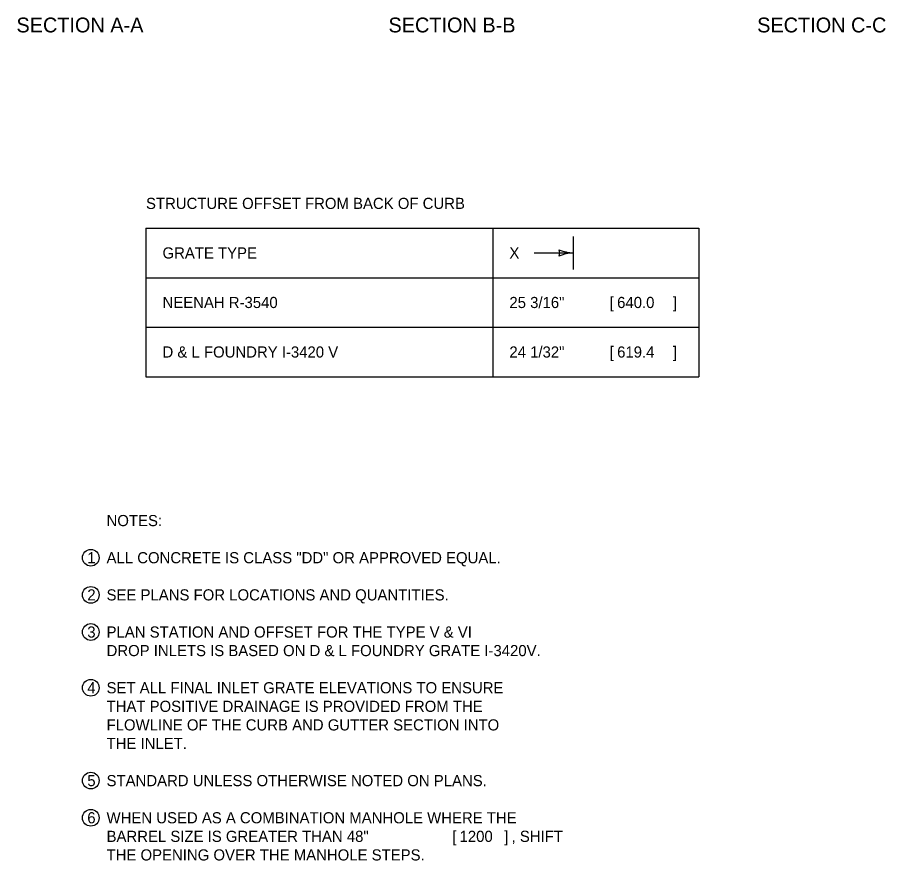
# Model space of a CAD drawing. Extents: x 49991.4 to 50041.6, y 49987.6 to 50011.4.
# Drawn here: x 50031.324 to 50035.997, y 49988.642 to 49993.182 of the extents above; entities that cross this region are included whole.
import ezdxf

# ---------------------------------------------------------------- set-up
doc = ezdxf.new("R2010")
doc.units = 0
doc.layers.add('Level 2', color=7, linetype='Continuous')
doc.layers.add('Level 3', color=7, linetype='Continuous')

msp = doc.modelspace()

# ---------------------------------------------------------------- linework, layer by layer
at = {"layer": 'Level 2'}
for p, q in [((50032.0163, 49992.0468), (50032.0163, 49991.2468)), ((50032.0163, 49992.0468), (50034.9914, 49992.0468)), ((50033.883, 49992.0468), (50033.883, 49991.2468)), ((50034.9914, 49992.0468), (50034.9914, 49991.2468)), ((50032.0163, 49991.7802), (50034.9914, 49991.7802)), ((50032.0163, 49991.5135), (50034.9914, 49991.5135)), ((50032.0163, 49991.2468), (50034.9914, 49991.2468))]:
    msp.add_line(p, q, dxfattribs=at)
for centre in [(50031.7191, 49990.2727), (50031.7191, 49990.0727), (50031.7191, 49989.8727), (50031.7191, 49989.5727), (50031.7191, 49989.0727), (50031.7191, 49988.8727)]:
    msp.add_circle(centre, 0.045, dxfattribs=at)
at = {"layer": 'Level 3'}
for p, q in [((50034.3163, 49991.8246), (50034.3163, 49992.0024)), ((50034.1047, 49991.9135), (50034.3163, 49991.9135))]:
    msp.add_line(p, q, dxfattribs=at)
for centre, radius, start, end in [((50034.3254, 49992.1356), 0.2223, 247.456, 267.6395), ((50034.1881, 49991.9135), 0.0548, 342.1388, 17.8612), ((50034.3278, 49991.6808), 0.233, 92.8273, 112.0772)]:
    msp.add_arc(centre, radius, start, end, dxfattribs=at)

# ---------------------------------------------------------------- texts
at = {"layer": 'Level 2'}
for s, height, p in [('SECTION A-A', 0.08, (50031.3192, 49993.1006)), ('SECTION B-B', 0.08, (50033.3212, 49993.1006)), ('SECTION C-C', 0.08, (50035.3052, 49993.1006)), ('STRUCTURE OFFSET FROM BACK OF CURB', 0.06, (50032.0163, 49992.1502)), ('GRATE TYPE       ', 0.06, (50032.1052, 49991.8835)), ('X', 0.06, (50033.9719, 49991.8835)), ('NEENAH R-3540', 0.06, (50032.1052, 49991.6168)), ('25 3/16" ', 0.06, (50033.9719, 49991.6168)), ('[', 0.06, (50034.5119, 49991.6168)), ('640.0', 0.06, (50034.5516, 49991.6168)), (']', 0.06, (50034.8516, 49991.6168)), ('D & L FOUNDRY I-3420 V', 0.06, (50032.1052, 49991.3502)), ('24 1/32" ', 0.06, (50033.9719, 49991.3502)), ('[', 0.06, (50034.5119, 49991.3502)), ('619.4', 0.06, (50034.5516, 49991.3502)), (']', 0.06, (50034.8516, 49991.3502)), ('NOTES:', 0.06, (50031.8041, 49990.4427)), ('1', 0.06, (50031.7004, 49990.2427)), ('ALL CONCRETE IS CLASS "DD" OR APPROVED EQUAL.', 0.06, (50031.8041, 49990.2427)), ('2', 0.06, (50031.7004, 49990.0427)), ('SEE PLANS FOR LOCATIONS AND QUANTITIES.', 0.06, (50031.8041, 49990.0427)), ('3', 0.06, (50031.7004, 49989.8427)), ('PLAN STATION AND OFFSET FOR THE TYPE V & VI', 0.06, (50031.8041, 49989.8427)), ('DROP INLETS IS BASED ON D & L FOUNDRY GRATE I-3420V.', 0.06, (50031.8041, 49989.7427)), ('4', 0.06, (50031.7004, 49989.5427)), ('SET ALL FINAL INLET GRATE ELEVATIONS TO ENSURE', 0.06, (50031.8041, 49989.5427)), ('THAT POSITIVE DRAINAGE IS PROVIDED FROM THE ', 0.06, (50031.8041, 49989.4427)), ('FLOWLINE OF THE CURB AND GUTTER SECTION INTO', 0.06, (50031.8041, 49989.3427)), ('THE INLET.', 0.06, (50031.8041, 49989.2427)), ('5', 0.06, (50031.7004, 49989.0427)), ('STANDARD UNLESS OTHERWISE NOTED ON PLANS.', 0.06, (50031.8041, 49989.0427)), ('6', 0.06, (50031.7004, 49988.8427)), ('WHEN USED AS A COMBINATION MANHOLE WHERE THE', 0.06, (50031.8041, 49988.8427)), ('BARREL SIZE IS GREATER THAN 48" ', 0.06, (50031.8041, 49988.7427)), ('[', 0.06, (50033.6641, 49988.7427)), ('1200', 0.06, (50033.7038, 49988.7427)), (']', 0.06, (50033.9438, 49988.7427)), (', SHIFT', 0.06, (50033.9835, 49988.7427)), ('THE OPENING OVER THE MANHOLE STEPS.', 0.06, (50031.8041, 49988.6427))]:
    msp.add_text(s, height=height, dxfattribs=at).set_placement(p)

doc.saveas('drawing.dxf')
